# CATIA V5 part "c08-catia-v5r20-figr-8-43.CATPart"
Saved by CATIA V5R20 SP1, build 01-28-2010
Part number: Part1
Bounding box of the stored display mesh (mm): x -50 to 50, y -50 to 50, z 0 to 25
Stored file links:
  D:\v5_r20\psrt_files_downloaded\c08-catia-v5r20-prt\c08-catia-v5r20-figr-8-43.CATPart
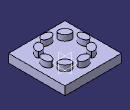
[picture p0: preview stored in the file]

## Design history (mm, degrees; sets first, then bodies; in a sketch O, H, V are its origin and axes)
Body1 (main body)
  Sketch1 on xy-plane, origin (0, 0, 0), H (1, 0, 0), V (0, 1, 0)
    line L1 (-50, 50) -> (50, 50)
    line L2 (50, 50) -> (50, -50)
    line L3 (50, -50) -> (-50, -50)
    line L4 (-50, -50) -> (-50, 50)
    axis line L5 (50, -50) -> (-50, 50)
    length L2 = 100
    length L3 = 100
    horizontal: L1 H, L3 H
    vertical: L2 V, L4 V
    midpoint: L5 O
  Pad1: profile Sketch1, direction (0, 0, 1), length 15
  Sketch2 on face of Pad1, origin (0, 0, 15), H (1, 0, 0), V (0, 1, 0)
    point P1 (0, -32.9864)
    ellipse A1 centre (0, -32.9864) semi-axes 9.9006, 6.5465 rotation 0
    point P2 (0, -26.4399)
    coincidence: P1 V, P2 V, A1 P2
  Pad2: profile Sketch2, direction (0, 0, 1), length 10
  CircPattern1: of Pad2, instances 8, angular step 45 {= 360.0*1 deg/CircPattern1.AngularNumber}, axis from edge of Sketch3
  Sketch3 on yz-plane, origin (0, 0, 0), H (0, 1, 0), V (0, 0, 1)
    line L1 (0, 0) -> (0, 18.4864)
    vertical: L1 V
